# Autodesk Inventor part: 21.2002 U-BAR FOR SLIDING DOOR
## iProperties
Created: 2007-05
Part Number: 21.2002 U-BAR FOR SLIDING DOOR
Material: Steel
Document SubType Name: Modeling
Designer: Andy Moles
Density: 7.85 g/cm^3
Author: Andy Moles
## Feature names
1. Base1
